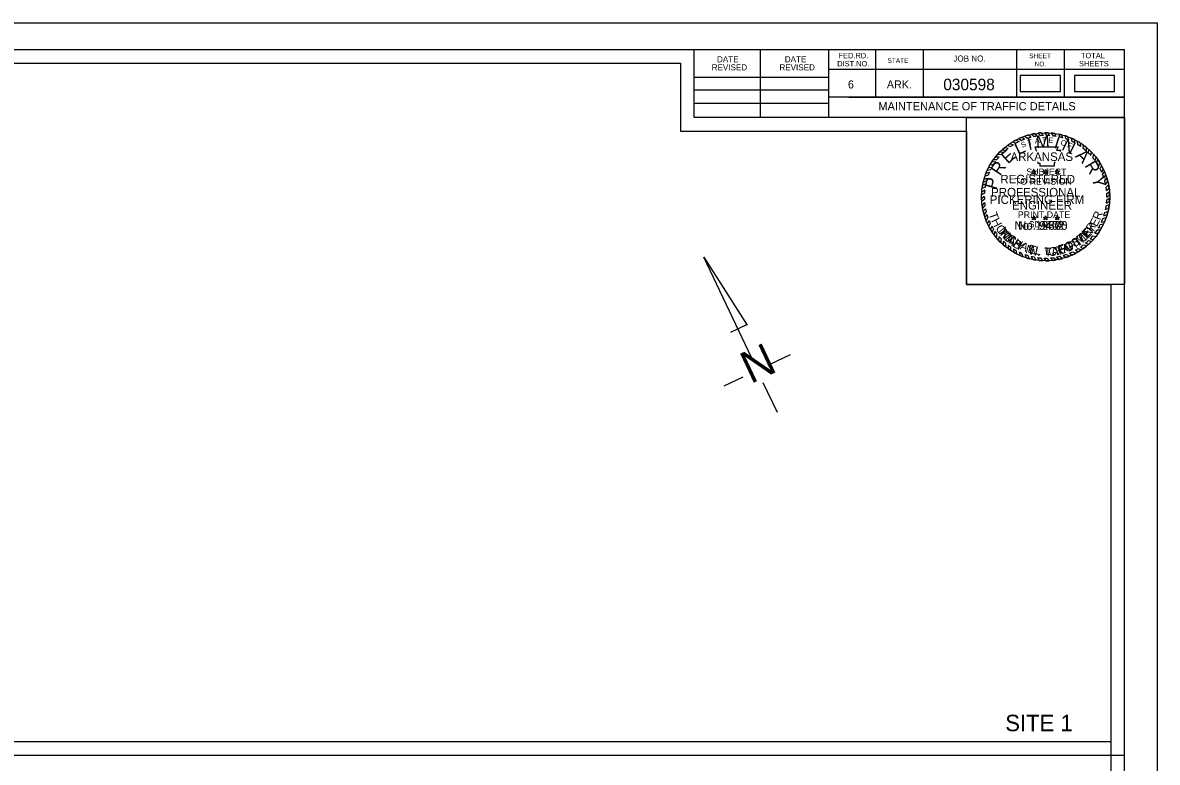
# Model space of a CAD drawing. Extents: x 1368648 to 1927880, y -1037443 to 380209.
# Drawn here: x 1378771 to 1379597, y 379215 to 379753 of the extents above; entities that cross this region are included whole.
import ezdxf

# ---------------------------------------------------------------- set-up
doc = ezdxf.new("R2010")
doc.units = 0
for name, color, linetype in [('Default', 7, 'Continuous'), ('R_Border', 7, 'Continuous'), ('R_Border Notes', 7, 'Continuous'), ('R_Border Title', 7, 'Continuous'), ('R_Draft', 7, 'Continuous'), ('R_No Plot', 7, 'Continuous'), ('STAMP_PE_CRAFTON', 7, 'Continuous'), ('STAMP_PE_FOSTER', 7, 'Continuous'), ('STAMP_PE_SEAL-INFO', 7, 'Continuous'), ('STAMP_PE_TAEGTMEYER', 7, 'Continuous'), ('STAMP_PE_TXT', 7, 'Continuous'), ('STAMP_PRELIMINARY', 7, 'Continuous')]:
    doc.layers.add(name, color=color, linetype=linetype)

msp = doc.modelspace()

# ---------------------------------------------------------------- linework, layer by layer
at = {"layer": 'Default'}
for points in [[(1379497.06, 379702.78), (1379526.22, 379702.78), (1379526.22, 379714.33), (1379497.06, 379714.33)], [(1379536.41, 379702.78), (1379565.57, 379702.78), (1379565.57, 379714.33), (1379536.41, 379714.33)]]:
    msp.add_lwpolyline(points, close=True, dxfattribs=at)
at = {"layer": 'R_Border'}
for p, q in [((1377992.09, 379733.26), (1379572.99, 379733.26)), ((1379259.79, 379683.86), (1379259.79, 379733.26)), ((1379308.19, 379683.86), (1379308.19, 379733.26)), ((1379357.49, 379733.26), (1379357.49, 379683.86)), ((1379391.69, 379733.26), (1379391.69, 379698.56)), ((1379426.39, 379733.26), (1379426.39, 379698.56)), ((1379494.29, 379733.26), (1379494.29, 379698.56)), ((1379528.99, 379733.26), (1379528.99, 379698.56)), ((1379572.99, 378705.96), (1379572.99, 379733.26)), ((1379572.99, 379718.56), (1379357.49, 379718.56)), ((1379572.99, 379718.66), (1379572.99, 379718.66)), ((1379259.79, 379713.16), (1379357.49, 379713.16)), ((1379259.79, 379703.86), (1379357.49, 379703.86)), ((1379572.99, 379698.56), (1379357.49, 379698.56)), ((1379372.29, 379698.56), (1379572.99, 379698.56)), ((1379259.79, 379694.16), (1379357.49, 379694.16)), ((1379572.99, 379683.86), (1379259.79, 379683.86)), ((1379572.99, 379219.61), (1377992.09, 379219.61))]:
    msp.add_line(p, q, dxfattribs=at)
at = {"layer": 'R_Draft'}
for p, q in [((1379266.98, 379582.19), (1379298.41, 379532.68)), ((1379301.71, 379508.63), (1379266.98, 379582.19)), ((1379286.53, 379527.56), (1379298.23, 379533.08)), ((1379315.09, 379504.34), (1379330, 379511.38)), ((1379281.61, 379488.53), (1379295.56, 379495.12)), ((1379320.34, 379469.16), (1379310.13, 379490.79))]:
    msp.add_line(p, q, dxfattribs=at)
at = {"layer": 'R_No Plot'}
for points in [[(1377930.05, 379752.73), (1379596.75, 379752.73), (1379596.75, 378686.04), (1377930.05, 378686.04)], [(1379562.99, 379229.61), (1378002.09, 379229.61), (1378002.09, 379723.26), (1379249.79, 379723.26), (1379249.79, 379673.86), (1379337.49, 379673.86), (1379457.99, 379673.86), (1379457.99, 379562.19), (1379562.99, 379562.19)], [(1379562.99, 379229.61), (1378002.09, 379229.61), (1378002.09, 379723.26), (1379249.79, 379723.26), (1379249.79, 379673.86), (1379337.49, 379673.86), (1379457.99, 379673.86), (1379457.99, 379562.19), (1379562.99, 379562.19)], [(1379562.99, 379229.61), (1378002.09, 379229.61), (1378002.09, 379723.26), (1379249.79, 379723.26), (1379249.79, 379673.86), (1379337.49, 379673.86), (1379457.99, 379673.86), (1379457.99, 379562.19), (1379562.99, 379562.19)], [(1379562.99, 379229.61), (1378002.09, 379229.61), (1378002.09, 379723.26), (1379249.79, 379723.26), (1379249.79, 379673.86), (1379337.49, 379673.86), (1379457.99, 379673.86), (1379457.99, 379562.19), (1379562.99, 379562.19)], [(1379562.99, 379229.61), (1378002.09, 379229.61), (1378002.09, 379723.26), (1379249.79, 379723.26), (1379249.79, 379673.86), (1379337.49, 379673.86), (1379457.99, 379673.86), (1379457.99, 379562.19), (1379562.99, 379562.19)], [(1379562.99, 379229.61), (1378002.09, 379229.61), (1378002.09, 379723.26), (1379249.79, 379723.26), (1379249.79, 379673.86), (1379337.49, 379673.86), (1379457.99, 379673.86), (1379457.99, 379562.19), (1379562.99, 379562.19)], [(1379562.99, 379229.61), (1378002.09, 379229.61), (1378002.09, 379723.26), (1379249.79, 379723.26), (1379249.79, 379673.86), (1379337.49, 379673.86), (1379457.99, 379673.86), (1379457.99, 379562.19), (1379562.99, 379562.19)], [(1378002.09, 379723.26), (1379249.79, 379723.26), (1379249.79, 379673.86), (1379337.49, 379673.86), (1379457.99, 379673.86), (1379457.99, 379562.19), (1379562.99, 379562.19), (1379562.99, 378715.96), (1378002.09, 378715.96)], [(1379457.99, 379683.86), (1379572.99, 379683.86), (1379572.99, 379562.19), (1379457.99, 379562.19)]]:
    msp.add_lwpolyline(points, close=True, dxfattribs=at)
at = {"layer": 'STAMP_PE_SEAL-INFO'}
for p, q in [((1379491.62, 379666.1), (1379493.78, 379664.99)), ((1379493.86, 379667.36), (1379496.17, 379666.23)), ((1379496.01, 379668.42), (1379497.96, 379667.04)), ((1379498.55, 379669.49), (1379500.02, 379667.87)), ((1379500.29, 379670.13), (1379502.19, 379668.61)), ((1379503.24, 379671.04), (1379504.68, 379669.31)), ((1379505.18, 379671.53), (1379506.96, 379669.81)), ((1379507.6, 379672.01), (1379509.09, 379670.17)), ((1379510.17, 379672.38), (1379511.58, 379670.46)), ((1379513.85, 379670.61), (1379512.29, 379672.57)), ((1379516.34, 379670.63), (1379514.95, 379672.68)), ((1379518.63, 379670.53), (1379517.34, 379672.65)), ((1379521.16, 379670.27), (1379519.7, 379672.49)), ((1379523.29, 379669.95), (1379522, 379672.23)), ((1379526.1, 379669.36), (1379525.23, 379671.65)), ((1379528.11, 379668.81), (1379527.31, 379671.16)), ((1379530.37, 379668.08), (1379529.66, 379670.48)), ((1379532.46, 379667.28), (1379531.73, 379669.76)), ((1379534.76, 379666.25), (1379534.25, 379668.74)), ((1379536.99, 379665.11), (1379536.56, 379667.65)), ((1379538.93, 379663.97), (1379538.73, 379666.48)), ((1379482.3, 379658.8), (1379485.02, 379658.59)), ((1379483.98, 379660.41), (1379486.27, 379659.72)), ((1379485.7, 379661.92), (1379488.34, 379661.41)), ((1379487.58, 379663.55), (1379489.86, 379662.53)), ((1379489.68, 379664.88), (1379491.89, 379663.87)), ((1379507.86, 379662.52), (1379524.58, 379662.52)), ((1379508.46, 379660.99), (1379507.86, 379662.52)), ((1379508.98, 379659.5), (1379508.46, 379660.99)), ((1379509.02, 379658.93), (1379508.98, 379659.5)), ((1379524.58, 379662.52), (1379523.45, 379660.07)), ((1379523.45, 379660.07), (1379526.61, 379660.07)), ((1379526.61, 379660.07), (1379525.89, 379658.93)), ((1379541.1, 379662.54), (1379540.95, 379665.12)), ((1379542.91, 379661.21), (1379543.08, 379663.64)), ((1379545.14, 379659.35), (1379545.24, 379661.96)), ((1379546.7, 379657.88), (1379547.05, 379660.38)), ((1379548.5, 379656.02), (1379548.83, 379658.65)), ((1379475.16, 379649.45), (1379477.61, 379649.55)), ((1379476.39, 379651.45), (1379478.98, 379651.62)), ((1379477.57, 379653.17), (1379480.09, 379653.15)), ((1379478.96, 379655.02), (1379481.7, 379655.13)), ((1379480.69, 379657.08), (1379483.29, 379656.88)), ((1379509.97, 379650.38), (1379509.84, 379651.47)), ((1379511.55, 379650.38), (1379509.97, 379650.38)), ((1379511.55, 379648.23), (1379511.55, 379650.38)), ((1379521.77, 379649.92), (1379521.69, 379648.23)), ((1379522.16, 379651.47), (1379521.77, 379649.92)), ((1379549.87, 379654.44), (1379550.55, 379656.79)), ((1379551.49, 379652.35), (1379552.16, 379654.85)), ((1379552.58, 379650.77), (1379553.47, 379653.09)), ((1379554.13, 379648.29), (1379555.04, 379650.74)), ((1379471.4, 379641.19), (1379473.82, 379641.87)), ((1379472.15, 379643.22), (1379474.67, 379643.95)), ((1379473.07, 379645.38), (1379475.58, 379645.9)), ((1379474.01, 379647.33), (1379476.5, 379647.65)), ((1379521.69, 379648.23), (1379511.55, 379648.23)), ((1379555.12, 379646.45), (1379556.26, 379648.68)), ((1379556.28, 379644.03), (1379557.41, 379646.46)), ((1379556.98, 379642.35), (1379558.3, 379644.52)), ((1379557.95, 379639.6), (1379559.31, 379641.98)), ((1379471.48, 379633.11), (1379469.26, 379632)), ((1379471.91, 379635.41), (1379469.59, 379634.16)), ((1379470.09, 379636.64), (1379472.44, 379637.6)), ((1379470.62, 379638.68), (1379473, 379639.52)), ((1379558.49, 379637.78), (1379559.96, 379640.04)), ((1379559.16, 379634.99), (1379560.75, 379637.22)), ((1379559.5, 379633.09), (1379561.27, 379634.85)), ((1379471.01, 379628.81), (1379468.9, 379627.53)), ((1379470.92, 379626.34), (1379468.9, 379624.67)), ((1379470.96, 379624.31), (1379469, 379622.68)), ((1379471.19, 379630.94), (1379469.01, 379629.53)), ((1379559.83, 379630.54), (1379561.7, 379632.22)), ((1379560, 379628.45), (1379561.95, 379629.91)), ((1379560, 379623.83), (1379562.1, 379625.22)), ((1379560.06, 379625.86), (1379562.08, 379627.47)), ((1379471.13, 379621.83), (1379469.27, 379620.05)), ((1379471.38, 379619.69), (1379469.61, 379617.82)), ((1379471.78, 379617.39), (1379470.08, 379615.55)), ((1379559.1, 379616.86), (1379561.37, 379617.84)), ((1379559.55, 379619.36), (1379561.77, 379620.46)), ((1379559.8, 379621.3), (1379561.97, 379622.59)), ((1379472.25, 379615.3), (1379470.68, 379613.22)), ((1379472.86, 379613.06), (1379471.39, 379610.97)), ((1379473.57, 379610.95), (1379472.16, 379608.89)), ((1379474.4, 379608.81), (1379473.09, 379606.7)), ((1379556.08, 379607.66), (1379558.52, 379608.14)), ((1379557.15, 379610.23), (1379559.56, 379610.89)), ((1379557.82, 379612.13), (1379560.28, 379613.14)), ((1379558.56, 379614.6), (1379560.92, 379615.61)), ((1379475.26, 379606.9), (1379474.12, 379604.59)), ((1379476.43, 379604.61), (1379475.48, 379602.16)), ((1379477.61, 379602.59), (1379476.69, 379600.23)), ((1379478.62, 379601.03), (1379478.07, 379598.27)), ((1379551.36, 379599.61), (1379553.88, 379599.63)), ((1379553.05, 379602.08), (1379555.44, 379602.05)), ((1379553.91, 379603.49), (1379556.42, 379603.76)), ((1379555.27, 379605.98), (1379557.71, 379606.32)), ((1379480.03, 379599.08), (1379479.52, 379596.42)), ((1379481.55, 379597.19), (1379481.11, 379594.59)), ((1379483.06, 379595.5), (1379482.75, 379592.89)), ((1379484.67, 379593.87), (1379484.52, 379591.23)), ((1379486.39, 379592.31), (1379486.38, 379589.67)), ((1379543.24, 379591.2), (1379545.58, 379590.47)), ((1379544.6, 379592.32), (1379546.95, 379591.67)), ((1379546.63, 379594.18), (1379548.83, 379593.49)), ((1379547.9, 379595.48), (1379550.29, 379595.05)), ((1379549.82, 379597.64), (1379552.13, 379597.24)), ((1379488.19, 379590.84), (1379488.29, 379588.22)), ((1379489.89, 379589.59), (1379490.07, 379587)), ((1379492.02, 379588.18), (1379492.32, 379585.62)), ((1379493.77, 379587.15), (1379494.23, 379584.59)), ((1379496.18, 379585.9), (1379496.96, 379583.3)), ((1379498.04, 379585.06), (1379498.91, 379582.51)), ((1379500.5, 379584.1), (1379501.55, 379581.59)), ((1379502.55, 379583.42), (1379503.68, 379580.98)), ((1379528.26, 379583.37), (1379530.34, 379581.88)), ((1379530.72, 379584.18), (1379532.93, 379582.84)), ((1379532.82, 379585.01), (1379534.93, 379583.7)), ((1379535.11, 379586.05), (1379537.53, 379584.99)), ((1379537.15, 379587.12), (1379539.23, 379585.95)), ((1379539.22, 379588.34), (1379541.47, 379587.37)), ((1379540.94, 379589.48), (1379543.13, 379588.54)), ((1379505.09, 379582.73), (1379506.15, 379580.4)), ((1379507.08, 379582.3), (1379508.31, 379580.01)), ((1379509.58, 379581.89), (1379510.78, 379579.69)), ((1379511.76, 379581.66), (1379513.13, 379579.51)), ((1379514.19, 379581.52), (1379515.7, 379579.46)), ((1379516.48, 379581.51), (1379518.2, 379579.53)), ((1379519.08, 379581.65), (1379520.71, 379579.75)), ((1379521.27, 379581.88), (1379523.13, 379580.09)), ((1379523.5, 379582.23), (1379525.44, 379580.53)), ((1379525.96, 379582.75), (1379527.85, 379581.12))]:
    msp.add_line(p, q, dxfattribs=at)
for radius, start, end in [(46.61, 117.65441, 120.80988), (44.57, 115.68692, 119.15827), (46.61, 111.31242, 114.70259), (44.57, 110.30864, 113.16588), (46.61, 105.23389, 109.03519), (44.57, 104.03521, 107.36155), (46.61, 99.75254, 102.77648), (44.57, 98.25799, 101.03289), (46.61, 93.93815, 96.55172), (44.57, 92.11016, 95.03666), (46.61, 87.72979, 90.67067), (44.57, 85.96279, 88.9097), (46.61, 81.97315, 84.82355), (44.57, 79.92642, 82.69597), (46.61, 75.31251, 77.94263), (44.57, 73.55748, 76.23144), (46.61, 69.60611, 72.30577), (44.57, 67.62483, 70.50398), (46.61, 63.13288, 66.2704), (44.57, 61.15575, 64.37837), (46.61, 56.90029, 60.09423), (46.61, 135.40208, 138.30314), (44.57, 133.13306, 136.25623), (46.61, 129.73259, 132.53764), (44.57, 127.52969, 130.96829), (46.61, 123.61993, 126.59063), (44.57, 121.97456, 125.11001), (44.57, 54.92383, 58.27016), (44.57, 48.30163, 52.03953), (46.61, 50.3492, 53.71593), (44.57, 42.22116, 45.55119), (46.61, 44.3405, 47.39292), (46.61, 147.00719, 149.89904), (46.61, 141.60556, 144.44865), (44.57, 145.01972, 148.21036), (44.57, 139.30101, 142.58729), (44.57, 36.13503, 39.53106), (46.61, 38.12472, 41.23157), (44.57, 29.90321, 33.66454), (46.61, 31.96138, 35.42937), (46.61, 158.40766, 161.07015), (46.61, 152.86398, 155.51889), (44.57, 156.34018, 159.23194), (44.57, 151.03153, 153.57304), (44.57, 23.77322, 27.22114), (46.61, 25.93909, 29.01247), (44.57, 17.68022, 21.42509), (46.61, 19.95381, 23.31409), (46.61, 170.0003, 172.68778), (46.61, 164.3068, 166.89395), (44.57, 167.90481, 170.90393), (44.57, 162.43309, 165.00133), (44.57, 11.54445, 15.23639), (44.57, 5.7599, 9.06056), (46.61, 13.84205, 17.44468), (46.61, 7.58519, 10.86211), (46.61, 175.74093, 178.2066), (46.61, 181.72508, 184.16255), (44.57, 179.64537, 182.26333), (44.57, 173.73, 176.47337), (44.57, 359.73289, 3.06392), (46.61, 1.72155, 4.72681), (46.61, 355.71562, 358.95694), (46.61, 187.42037, 190.19271), (44.57, 185.45389, 188.23401), (44.57, 191.22736, 193.98583), (44.57, 348.07782, 351.34355), (44.57, 353.86319, 357.12742), (46.61, 349.83047, 353.08845), (46.61, 193.03695, 195.99732), (46.61, 198.89671, 201.62812), (44.57, 196.96751, 199.83526), (44.57, 202.77613, 205.47915), (44.57, 335.6038, 339.18578), (44.57, 341.77699, 345.09248), (46.61, 337.38367, 340.99332), (46.61, 343.89247, 347.03502), (46.61, 204.54793, 207.43282), (46.61, 210.86355, 213.65709), (44.57, 208.78826, 211.79343), (44.57, 214.18375, 217.27474), (44.57, 323.58513, 327.44069), (46.61, 325.44052, 328.98725), (44.57, 329.55488, 333.20757), (46.61, 331.40371, 334.93315), (46.61, 216.61154, 219.49098), (46.61, 222.47995, 225.38008), (44.57, 220.39088, 223.30564), (46.61, 228.36648, 231.34802), (44.57, 226.24938, 229.24068), (44.57, 304.82299, 308.51428), (44.57, 310.77436, 314.31605), (46.61, 312.45177, 315.66328), (44.57, 316.65308, 320.37109), (46.61, 318.28455, 321.80429), (44.57, 232.22904, 234.93361), (46.61, 234.29502, 236.94517), (44.57, 238.22227, 240.83529), (46.61, 240.1977, 242.86128), (44.57, 244.32043, 246.94859), (46.61, 246.57598, 249.15579), (44.57, 250.34912, 253.12157), (44.57, 286.64233, 289.97826), (44.57, 292.87452, 296.11851), (46.61, 294.64808, 298.21662), (44.57, 299.07679, 302.17235), (46.61, 300.62101, 303.87026), (46.61, 306.37206, 310.20799), (46.61, 252.59667, 255.32518), (44.57, 256.50505, 259.11916), (46.61, 258.44328, 261.13983), (44.57, 262.37828, 265.20115), (46.61, 264.19784, 267.10092), (44.57, 268.3215, 271.27698), (46.61, 270.25484, 273.33609), (44.57, 274.61565, 277.44863), (46.61, 276.42389, 279.43574), (44.57, 280.34588, 283.58137), (46.61, 282.31994, 285.37019), (46.61, 288.57086, 291.97334)]:
    msp.add_arc((1379515.49, 379626.07), radius, start, end, dxfattribs=at)
at = {"layer": 'STAMP_PE_TXT'}
for p, q in [((1379506.39, 379643.93), (1379505.4, 379644.65)), ((1379505.4, 379644.65), (1379506.62, 379644.65)), ((1379506.01, 379642.76), (1379506.39, 379643.93)), ((1379507, 379643.48), (1379506.01, 379642.76)), ((1379506.62, 379644.65), (1379507, 379645.81)), ((1379507, 379645.81), (1379507.38, 379644.65)), ((1379507.99, 379642.76), (1379507, 379643.48)), ((1379507.38, 379644.65), (1379508.61, 379644.65)), ((1379508.61, 379644.65), (1379507.61, 379643.93)), ((1379507.61, 379643.93), (1379507.99, 379642.76)), ((1379514.88, 379643.93), (1379513.89, 379644.65)), ((1379513.89, 379644.65), (1379515.11, 379644.65)), ((1379514.5, 379642.76), (1379514.88, 379643.93)), ((1379515.49, 379643.48), (1379514.5, 379642.76)), ((1379515.11, 379644.65), (1379515.49, 379645.81)), ((1379515.49, 379645.81), (1379515.87, 379644.65)), ((1379516.48, 379642.76), (1379515.49, 379643.48)), ((1379515.87, 379644.65), (1379517.1, 379644.65)), ((1379517.1, 379644.65), (1379516.1, 379643.93)), ((1379516.1, 379643.93), (1379516.48, 379642.76)), ((1379523.37, 379643.93), (1379522.38, 379644.65)), ((1379522.38, 379644.65), (1379523.6, 379644.65)), ((1379522.99, 379642.76), (1379523.37, 379643.93)), ((1379523.98, 379643.48), (1379522.99, 379642.76)), ((1379523.6, 379644.65), (1379523.98, 379645.81)), ((1379523.98, 379645.81), (1379524.36, 379644.65)), ((1379524.97, 379642.76), (1379523.98, 379643.48)), ((1379524.36, 379644.65), (1379525.59, 379644.65)), ((1379525.59, 379644.65), (1379524.59, 379643.93)), ((1379524.59, 379643.93), (1379524.97, 379642.76)), ((1379506.39, 379610.39), (1379505.4, 379611.11)), ((1379505.4, 379611.11), (1379506.62, 379611.11)), ((1379506.01, 379609.22), (1379506.39, 379610.39)), ((1379507, 379609.95), (1379506.01, 379609.22)), ((1379506.62, 379611.11), (1379507, 379612.28)), ((1379507, 379612.28), (1379507.38, 379611.11)), ((1379507.99, 379609.22), (1379507, 379609.95)), ((1379507.38, 379611.11), (1379508.61, 379611.11)), ((1379508.61, 379611.11), (1379507.61, 379610.39)), ((1379507.61, 379610.39), (1379507.99, 379609.22)), ((1379514.88, 379610.39), (1379513.89, 379611.11)), ((1379513.89, 379611.11), (1379515.11, 379611.11)), ((1379514.5, 379609.22), (1379514.88, 379610.39)), ((1379515.49, 379609.95), (1379514.5, 379609.22)), ((1379515.11, 379611.11), (1379515.49, 379612.28)), ((1379515.49, 379612.28), (1379515.87, 379611.11)), ((1379516.48, 379609.22), (1379515.49, 379609.95)), ((1379515.87, 379611.11), (1379517.1, 379611.11)), ((1379517.1, 379611.11), (1379516.1, 379610.39)), ((1379516.1, 379610.39), (1379516.48, 379609.22)), ((1379523.37, 379610.39), (1379522.38, 379611.11)), ((1379522.38, 379611.11), (1379523.6, 379611.11)), ((1379522.99, 379609.22), (1379523.37, 379610.39)), ((1379523.98, 379609.95), (1379522.99, 379609.22)), ((1379523.6, 379611.11), (1379523.98, 379612.28)), ((1379523.98, 379612.28), (1379524.36, 379611.11)), ((1379524.97, 379609.22), (1379523.98, 379609.95)), ((1379524.36, 379611.11), (1379525.59, 379611.11)), ((1379525.59, 379611.11), (1379524.59, 379610.39)), ((1379524.59, 379610.39), (1379524.97, 379609.22))]:
    msp.add_line(p, q, dxfattribs=at)
at = {"layer": 'STAMP_PRELIMINARY'}
msp.add_circle((1379515.49, 379626.07), 46.61, dxfattribs=at)

# ---------------------------------------------------------------- texts
at = {"layer": 'R_Border'}
for s, height, p in [('DATE', 4.396, (1379276.48, 379723.94)), ('DATE', 4.396, (1379325.78, 379723.94)), ('DIST.NO.', 3.91, (1379363.89, 379720.96)), ('FED.RD.', 3.91, (1379364.89, 379726.86)), ('STATE', 3.42, (1379400.49, 379723.46)), ('JOB NO.', 4.396, (1379448.39, 379724.46)), ('SHEET', 3.42, (1379503.59, 379726.86)), ('NO.', 3.42, (1379507.49, 379720.96)), ('SHEETS', 3.91, (1379539.79, 379720.96)), ('TOTAL', 3.91, (1379541.19, 379726.86)), ('REVISED', 4.396, (1379272.58, 379718.04)), ('REVISED', 4.396, (1379321.88, 379718.04)), ('6', 5.86, (1379371.69, 379704.86)), ('ARK.', 5.861, (1379399.99, 379704.86))]:
    msp.add_text(s, height=height, dxfattribs=at).set_placement(p)
at = {"layer": 'R_Border Notes'}
for s, height, p in [('030598', 8.4, (1379441.05, 379703.58)), ('MAINTENANCE OF TRAFFIC DETAILS', 6, (1379393.84, 379688.95))]:
    msp.add_text(s, height=height, dxfattribs=at).set_placement(p)
at = {"layer": 'R_Border Title'}
msp.add_text('SITE 1', height=12, dxfattribs=at).set_placement((1379486.16, 379237.23))
at = {"layer": 'R_Draft'}
msp.add_text('N', height=23.27, rotation=25.27231, dxfattribs=at).set_placement((1379300.89, 379489.71))
at = {"layer": 'STAMP_PE_CRAFTON'}
msp.add_text('No. 12370', height=6.25, dxfattribs=at).set_placement((1379492.8, 379602.05))
for s, rotation, p in [('T', 310.74416, (1379480.32, 379600.56)), ('O', 317.64216, (1379483.66, 379596.5)), ('O', 41.83906, (1379542.67, 379592.27)), ('N', 49.24107, (1379546.9, 379596.18)), ('N', 324.45371, (1379487.89, 379592.58)), ('Y', 331.16864, (1379493.05, 379589)), ('A', 20.51248, (1379528.9, 379584.85)), ('F', 28.78207, (1379533.8, 379586.72)), ('T', 34.11362, (1379538.37, 379589.26)), ('N', 347.47515, (1379503.32, 379584.42)), ('.', 356.89262, (1379509.47, 379583.03)), ('C', 6.01169, (1379517.85, 379582.77)), ('R', 14.81888, (1379523.33, 379583.35))]:
    msp.add_text(s, height=6.25, rotation=rotation, dxfattribs=at).set_placement(p)
at = {"layer": 'STAMP_PE_FOSTER'}
msp.add_text('No. 9402', height=6.25, dxfattribs=at).set_placement((1379495.42, 379602.05))
for s, rotation, p in [('M', 308.33902, (1379481.07, 379601.18)), ('I', 314.18423, (1379485.06, 379596.49)), ('T', 39.41938, (1379541.2, 379592.27)), ('E', 46.96131, (1379545.49, 379596.02)), ('R', 54.5031, (1379549.11, 379600.12)), ('C', 319.87327, (1379486.83, 379594.72)), ('H', 327.72349, (1379491.48, 379591.04)), ('A', 335.72761, (1379496.38, 379588.13)), ('E', 343.5779, (1379502.07, 379585.78)), ('F', 15.86908, (1379525.67, 379584.84)), ('O', 23.71897, (1379530.89, 379586.48)), ('S', 31.72336, (1379536.44, 379589.13)), ('L', 350.81148, (1379507.36, 379584.39)), ('L', 1.26658, (1379515.06, 379583.61)), ('.', 6.80354, (1379520.29, 379583.9))]:
    msp.add_text(s, height=6, rotation=rotation, dxfattribs=at).set_placement(p)
at = {"layer": 'STAMP_PE_TAEGTMEYER'}
for s, rotation, p in [('T', 289.64597, (1379473.96, 379613.62)), ('H', 296.73386, (1379475.76, 379608.7)), ('E', 63.0984, (1379552.72, 379603.73)), ('R', 69.57001, (1379555.22, 379608.64)), ('O', 303.77078, (1379478.73, 379603.16)), ('M', 314.20329, (1379482, 379598.4)), ('E', 46.80938, (1379545.68, 379594.95)), ('Y', 53.99864, (1379549.38, 379599.03)), ('A', 321.0594, (1379486.81, 379593.58)), ('S', 327.82385, (1379490.94, 379590.36)), ('E', 17.68363, (1379525.24, 379583.73)), ('G', 23.30524, (1379530.49, 379585.38)), ('T', 31.46601, (1379535.99, 379587.84)), ('M', 39.30005, (1379540.48, 379590.56)), ('N', 344.27273, (1379500.42, 379585.33)), ('.', 350.64643, (1379506.49, 379583.67)), ('T', 3.00609, (1379514.81, 379582.67)), ('A', 8.98261, (1379520.05, 379582.95))]:
    msp.add_text(s, height=6.25, rotation=rotation, dxfattribs=at).set_placement(p)
msp.add_text('No. 19605', height=6.25, dxfattribs=at).set_placement((1379492.8, 379602.05))
at = {"layer": 'STAMP_PE_TXT'}
for s, rotation, p in [('S', 23.5541, (1379498.49, 379661.59)), ('T', 16.311, (1379503.1, 379663.45)), ('A', 9.0679, (1379507.91, 379664.71)), ('T', 1.82479, (1379512.84, 379665.36)), ('E', 355.20019, (1379517.39, 379665.4)), ('O', 342.25065, (1379526.03, 379664.02)), ('F', 335.00755, (1379530.85, 379662.33))]:
    msp.add_text(s, height=3.91, rotation=rotation, dxfattribs=at).set_placement(p)
for s, p in [('ARKANSAS', (1379489.95, 379652.12)), ('REGISTERED', (1379482.57, 379635.77)), ('PROFESSIONAL', (1379475.83, 379626.27)), ('ENGINEER', (1379491.04, 379616.76))]:
    msp.add_text(s, height=6.25, dxfattribs=at).set_placement(p)
at = {"layer": 'STAMP_PRELIMINARY'}
for s, rotation, p in [('I', 12.52485, (1379503.18, 379660)), ('M', 3.10738, (1379508.67, 379661.55)), ('I', 342.31637, (1379521.01, 379661.88)), ('N', 333.9382, (1379526.55, 379660.51)), ('E', 42.35784, (1379488.12, 379649.55)), ('L', 25.51305, (1379495.54, 379656.21)), ('A', 315.65789, (1379536.72, 379655.39)), ('R', 56.22922, (1379482.34, 379640.89)), ('R', 301.38306, (1379543.56, 379648.82)), ('Y', 283.25926, (1379549, 379639.88)), ('P', 73.91301, (1379479.6, 379630.77))]:
    msp.add_text(s, height=9, rotation=rotation, dxfattribs=at).set_placement(p)
for s, height, p in [('SUBJECT', 4.8, (1379501.49, 379641.81)), ('TO REVISION', 4.8, (1379493.17, 379634.89)), ('PICKERING FIRM', 6.25, (1379474.86, 379620.88)), ('PRINT DATE', 4.8, (1379495.28, 379610.65)), ('$DATE$', 4.8, (1379503.66, 379603.72))]:
    msp.add_text(s, height=height, dxfattribs=at).set_placement(p)

doc.saveas('drawing.dxf')
